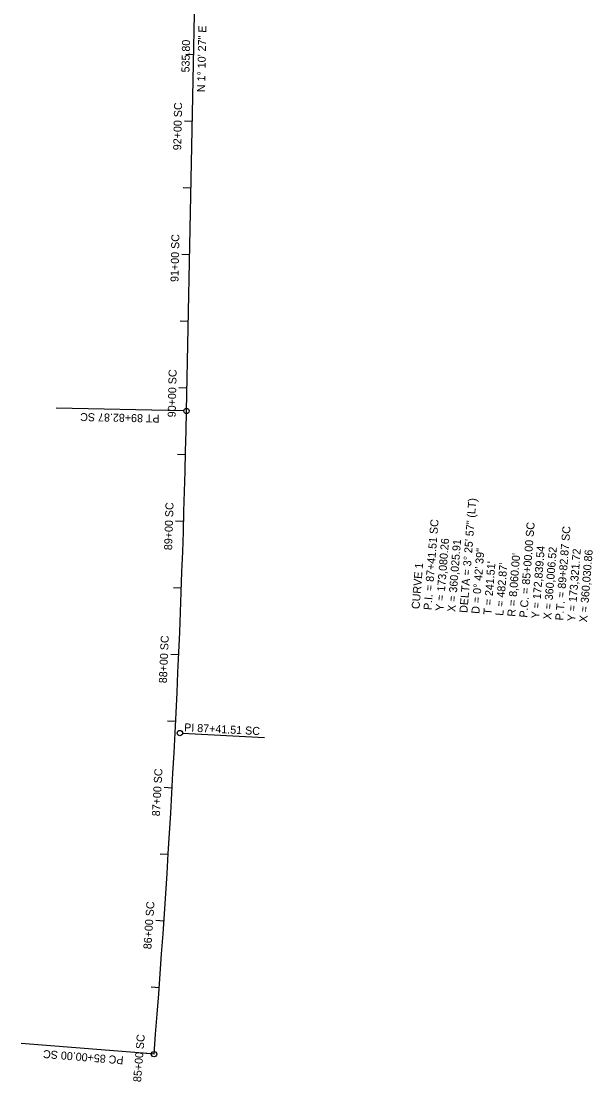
# Model space of a CAD drawing. Extents: x 356161 to 360393, y 172819 to 199204.
# Drawn here: x 359907 to 360335, y 172819 to 173614 of the extents above; entities that cross this region are included whole.
import ezdxf

# ---------------------------------------------------------------- set-up
doc = ezdxf.new("R2010")
doc.units = 0
for name, color, linetype in [('CA-MTCH-LINE', 7, 'Continuous'), ('CA-MTCH-LINE-TEXT', 7, 'Continuous'), ('Default', 7, 'Continuous'), ('Level 28', 7, 'Continuous'), ('P_PM_DotLane_50', 7, 'Continuous'), ('P_TC_Text', 7, 'Continuous')]:
    doc.layers.add(name, color=color, linetype=linetype)

msp = doc.modelspace()

# ---------------------------------------------------------------- linework, layer by layer
at = {"layer": 'CA-MTCH-LINE-TEXT'}
for p, q in [((360036.34, 173588.79), (360030.34, 173588.92)), ((360035.31, 173538.81), (360029.31, 173538.93)), ((360034.29, 173488.82), (360028.29, 173488.94)), ((360033.26, 173438.83), (360027.26, 173438.95)), ((360032.24, 173388.84), (360026.24, 173388.96)), ((360031.21, 173338.85), (360025.21, 173338.97)), ((360030.12, 173288.86), (360024.12, 173289.01)), ((360028.74, 173238.88), (360022.74, 173239.06)), ((360027.04, 173188.91), (360021.05, 173189.13)), ((360025.04, 173138.95), (360019.05, 173139.21)), ((360022.73, 173089), (360016.74, 173089.3)), ((360020.1, 173039.07), (360014.11, 173039.4)), ((360017.17, 172989.16), (360011.18, 172989.53)), ((360013.93, 172939.26), (360007.94, 172939.67)), ((360010.38, 172889.39), (360004.39, 172889.83)), ((360006.52, 172839.54), (360000.54, 172840.02))]:
    msp.add_line(p, q, dxfattribs=at)
at = {"layer": 'Level 28'}
for p, q in [((360028.86, 173321.76), (359933.24, 173323.72)), ((360027.91, 173080.16), (360089.38, 173077.06)), ((360004.52, 172839.7), (359906.99, 172847.56))]:
    msp.add_line(p, q, dxfattribs=at)
for centre in [(360030.86, 173321.72), (360025.91, 173080.26), (360006.52, 172839.54)]:
    msp.add_circle(centre, 2, dxfattribs=at)
at = {"layer": 'P_PM_DotLane_50'}
msp.add_line((360030.86, 173321.72), (360041.84, 173857.41), dxfattribs=at)
msp.add_arc((351972.56, 173486.9), 8060, 355.393179, 358.825735, dxfattribs=at)

# ---------------------------------------------------------------- texts
at = {"layer": 'CA-MTCH-LINE'}
for s, rotation, p in [('92+00 SC', 88.82573, (360026.87, 173517.12)), ('91+00 SC', 88.82573, (360024.84, 173418.37)), ('90+00 SC', 88.82573, (360022.76, 173316.93)), ('89+00 SC', 88.23664, (360020.07, 173217.29)), ('88+00 SC', 87.52578, (360016.11, 173117.51)), ('87+00 SC', 86.81491, (360010.91, 173017.75)), ('86+00 SC', 86.10404, (360004.47, 172918.05)), ('85+00 SC', 85.39318, (359996.79, 172818.45))]:
    msp.add_text(s, height=6, rotation=rotation, dxfattribs=at).set_placement(p)
at = {"layer": 'Default'}
for s, p in [('N 1%%d 10\' 27" E', (360044.76, 173560.62)), ('535.80', (360033.06, 173575.43))]:
    msp.add_text(s, height=6, rotation=88.82573, dxfattribs=at).set_placement(p)
at = {"layer": 'Level 28'}
for s, rotation, p in [('PT 89+82.87 SC', 178.82573, (360010.79, 173318.99)), ('PI 87+41.51 SC', 357.10946, (360028.99, 173081.61)), ('PC 85+00.00 SC', 175.39318, (359983.89, 172837.89))]:
    msp.add_text(s, height=6, rotation=rotation, dxfattribs=at).set_placement(p)
at = {"layer": 'P_TC_Text'}
for s, p in [('DELTA = 3%%d 25\' 57" (LT)', (360241.37, 173170.18)), ('P.I. = 87+41.51 SC', (360214.45, 173172.31)), ('P.C. = 85+00.00 SC', (360286.23, 173166.63)), ('P.T. = 89+82.87 SC', (360313.15, 173164.5)), ('Y = 173,080.26', (360223.43, 173171.6)), ('X = 360,025.91', (360232.4, 173170.89)), ('D = 0%%d 42\' 39"', (360250.34, 173169.47)), ("R = 8,060.00'", (360277.26, 173167.34)), ('Y = 172,839.54', (360295.2, 173165.92)), ('X = 360,006.52', (360304.17, 173165.21)), ('Y = 173,321.72', (360322.12, 173163.79)), ('X = 360,030.86', (360331.09, 173163.08)), ('CURVE 1', (360205.48, 173173.02)), ("T = 241.51'", (360259.31, 173168.76)), ("L = 482.87'", (360268.29, 173168.05))]:
    msp.add_text(s, height=6, rotation=85.476, dxfattribs=at).set_placement(p)

doc.saveas('drawing.dxf')
